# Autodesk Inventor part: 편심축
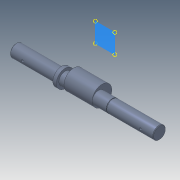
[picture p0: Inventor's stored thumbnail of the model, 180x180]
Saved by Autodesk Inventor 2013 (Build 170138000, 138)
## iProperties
Manager: 한국ATC센터
Company: 한국ATC센터
Created: 2014-10
Part Number: 편심축
Document SubType Name: Modeling
Designer: 한국ATC센터
Density: 7.86 g/cm^3
Material: 강, 연강
Mass: 1420.77 g
Surface Area: 286.549 cm^2
Volume: 180.76 cm^3
Author: KYOUNG IL JANG
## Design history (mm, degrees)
sketch "스케치1"
  geometry: L1 (-142, 0)-(142, 0); L2 (-142, 0)-(-142, 12.5); L3 (-142, 12.5)-(-52, 12.5); L4 (-52, 12.5)-(-52, 17.5); L5 (-52, 17.5)-(-45, 17.5); L6 (-45, 17.5)-(-45, 12.5); L7 (-45, 12.5)-(48.65, 12.5); L8 (48.65, 12.5)-(48.65, 11.95); L9 (48.65, 11.95)-(50, 11.95); L10 (50, 11.95)-(50, 12.5); L11 (50, 12.5)-(142, 12.5); L12 (142, 12.5)-(142, 0); L13 (109, 12.5)-(109, 9.1); L14 (109, 9.1)-(134, 9.1); L15 (134, 9.1)-(134, 12.5); L16 (117, -12.5)-(119.5, -12.5); L17 (119.5, -12.5)-(117, -10); L18 (117, -10)-(117, -12.5); L19 (-109, 12.5)-(-109, 9.1); L20 (-109, 9.1)-(-134, 9.1); L21 (-134, 9.1)-(-134, 12.5); L22 (-117, -12.5)-(-117, -10); L23 (-117, -10)-(-114.5, -12.5); L24 (-114.5, -12.5)-(-117, -12.5); 2 further points
  constraints: 48 end point, 11 parallel, 8 perpendicular, 5 collinear, 4 point on line, 1 coincident, 1 horizontal, 1 midpoint, 1 vertical
  dimensions: "d0" = 284 distance of L1.start L1.end (derived); "d1" = 25 diameter of L3 L1; "d2" = 35 diameter of L5 L1; "d3" = 90 distance of L2.end L3.end; "d4" = 187 distance between parallel lines of L12 L6; "d6" = 1.35 distance of L8.end L9.end; "d7" = 23.9 diameter of L9 L1; "d8" = 3.4 distance between parallel lines of L14 L11; "d9" = 8 distance between parallel lines of L15 L12; "d10" = 25 distance of L13.end L14.end; "d11" = 25 diameter of L16 L1 (= d1); "d12" = 25 distance from line of L12 L16.start; "d13" = 45 deg angle of L17 L18; "d14" = 5 diameter of L16.end L18; "d27" = 92 distance between parallel lines of L10 L12; "d32" = 7 distance of L4.end L5.end; "d33" = 8 distance between parallel lines of L2 L21; "d34" = 25 distance between parallel lines of L21 L19; "d35" = 3.4 distance between parallel lines of L3 L20; "d36" = 25 distance from line of L22.start L2; "d37" = 5 diameter of L23.end L22
revolve "회전1" stored, may be unused: angle "d15" = 90 deg
revolve "회전2" stored, may be unused: angle "d16" = 90 deg
revolve "회전3" stored, may be unused: angle "d38" = 90 deg
extrude "돌출1" cut sketch "스케치1" stored distance "d17" = 8; taper "d18" = 0 deg
fillet "모깎기1" dims "d19" = 4
node "작업 평면1"
sketch "스케치2"
  geometry: C1 r 12.5 at (0, 0) reference; C2 r 19.5 at (0, 7); 1 further point
  constraints: 1 centre point, 1 tangent, 1 vertical alignment
  dimensions: "d21" = 7 distance of point (0, 0) C2.centre; "d30" = 39 diameter of C2 (derived)
extrude "돌출2" join sketch "스케치2" distance "d22" = 56; taper "d23" = 0 deg
chamfer "모따기1" distance "d24" = 1; stored, may be unused: second distance "d25" = 2, angle "d26" = 45 deg
node "솔리드1"
other parameters: "d20" = 16
